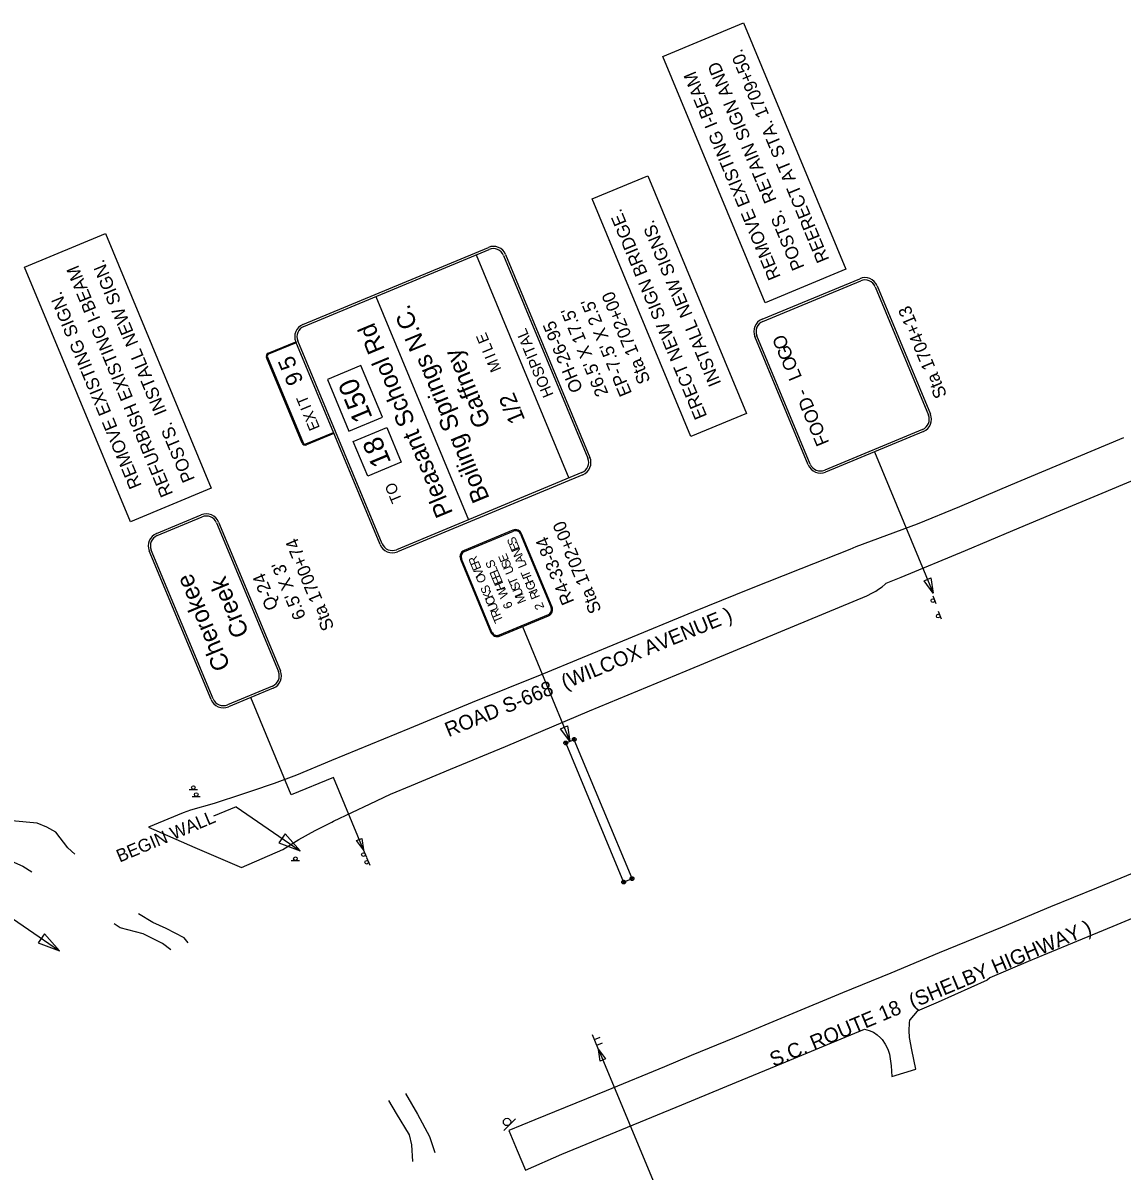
# Model space of a CAD drawing. Extents: x 1816080 to 1817753, y 1191002 to 1192408.
# Drawn here: x 1816561 to 1817158, y 1191507 to 1192132 of the extents above; entities that cross this region are included whole.
import ezdxf

# ---------------------------------------------------------------- set-up
doc = ezdxf.new("R2010")
doc.units = 0
for name, color, linetype in [('RD_EX_H2O', 7, 'Continuous'), ('RD_EX_Road', 7, 'Continuous'), ('RD_PD_Final_TX', 7, 'Continuous'), ('RD_TX_RoadID', 7, 'Continuous'), ('SN_P_Signs', 7, 'Continuous'), ('TERMINATOR', 7, 'Continuous')]:
    doc.layers.add(name, color=color, linetype=linetype)

msp = doc.modelspace()

# ---------------------------------------------------------------- linework, layer by layer
at = {"layer": 'RD_EX_H2O'}
for points in [[(1816589, 1191679.78), (1816585.25, 1191683.2), (1816578.74, 1191691.77), (1816573.75, 1191694.47), (1816568.64, 1191696.6), (1816554.75, 1191697.91), (1816541.33, 1191701.27), (1816538.68, 1191702.62), (1816532.83, 1191708.56), (1816530.28, 1191709.54), (1816524.78, 1191709.72), (1816522.41, 1191709.25)], [(1816520.29, 1191693.6), (1816530.82, 1191691.49), (1816535.64, 1191689.78), (1816539.88, 1191686.46), (1816543.67, 1191682.18), (1816552.98, 1191676.66), (1816560.73, 1191673.18), (1816565.63, 1191670.1)], [(1816650.69, 1191631.6), (1816648.48, 1191634.22), (1816638.79, 1191639.27), (1816631.49, 1191642.56), (1816623.69, 1191647.26)], [(1816641.27, 1191627.68), (1816636.63, 1191631.24), (1816626.22, 1191636.42), (1816613.77, 1191639.59), (1816610.48, 1191641.82)], [(1816772.91, 1191512.59), (1816772.31, 1191521.59), (1816770.96, 1191527.01), (1816763.86, 1191538.77), (1816759.76, 1191545.79)], [(1816768.75, 1191549.52), (1816775.4, 1191538.37), (1816781.92, 1191526.15), (1816784.51, 1191518.57), (1816784.74, 1191517.47)]]:
    msp.add_lwpolyline(points, dxfattribs=at)
at = {"layer": 'RD_EX_Road'}
for points in [[(1817159.28, 1191906.27), (1817133.62, 1191895.47), (1817097.75, 1191880.38), (1817070, 1191868.72), (1817046.98, 1191859.18), (1817013.79, 1191846.89), (1817010.39, 1191845.48), (1816983.85, 1191834.92), (1816955.91, 1191823.87), (1816925.5, 1191811.48), (1816886.89, 1191795.51), (1816842.95, 1191777.48), (1816805.13, 1191762.22), (1816770.95, 1191748.17), (1816728.58, 1191730.62), (1816709.5, 1191722.66), (1816697.39, 1191718.14), (1816685.15, 1191713.99), (1816680.25, 1191712.44), (1816664.73, 1191707.29), (1816651.93, 1191703.61), (1816648.02, 1191702.29), (1816629.17, 1191694.48), (1816654.27, 1191683.4), (1816679.72, 1191672.57), (1816702.06, 1191682.35), (1816710.8, 1191687.65), (1816719.74, 1191692.61), (1816728.86, 1191697.23), (1816729.67, 1191697.62), (1816749.54, 1191707.18), (1816760.69, 1191712.36), (1816772.09, 1191717.17), (1816793.24, 1191725.98), (1816823.15, 1191738.29), (1816868.84, 1191757.71), (1816921.52, 1191779.54), (1816972.94, 1191800.93), (1817019.73, 1191820.32), (1817022.74, 1191821.91), (1817024.61, 1191822.88), (1817026.09, 1191823.82), (1817027.98, 1191825.06), (1817029.63, 1191826.61), (1817030.13, 1191827.2), (1817038.28, 1191830.49), (1817073.38, 1191844.99), (1817099.07, 1191855.87), (1817122.78, 1191865.77), (1817147.59, 1191876.11), (1817172.24, 1191886.42)], [(1817167.93, 1191670.92), (1817144.65, 1191661.34), (1817119.54, 1191651.03), (1817093.24, 1191640.1), (1817059.06, 1191626), (1817032.77, 1191615.07), (1817006.46, 1191604.26), (1816977.23, 1191592.23), (1816947.67, 1191579.89), (1816924.09, 1191570.24), (1816909.61, 1191564.09), (1816877.97, 1191550.97), (1816839.15, 1191535.23), (1816824.95, 1191529.39), (1816829.5, 1191518.62), (1816834.02, 1191507.96), (1816853.9, 1191516.54), (1816919.09, 1191543.42), (1816934.01, 1191549.55), (1816948.82, 1191555.7), (1816973.39, 1191565.89), (1816998.28, 1191576.15), (1817018.5, 1191584.55)], [(1817174.36, 1191649.05), (1817153.46, 1191640.32), (1817128.43, 1191630.1), (1817107.43, 1191621.45), (1817086.59, 1191612.47), (1817085.14, 1191611.22), (1817058.42, 1191599.3), (1817047.13, 1191594.32), (1817043.08, 1191589.67)], [(1817018.5, 1191584.55), (1817020.94, 1191583.89), (1817023.23, 1191582.86), (1817025.34, 1191581.48), (1817027.21, 1191579.78), (1817027.96, 1191578.93), (1817029.71, 1191576.39), (1817031.11, 1191573.66), (1817032.09, 1191571.01), (1817032.92, 1191564.55), (1817033.32, 1191558.82), (1817046.4, 1191562.74), (1817044.12, 1191573.35), (1817042.9, 1191579.97), (1817042.68, 1191583.86), (1817042.85, 1191587.75), (1817043.08, 1191589.67)]]:
    msp.add_lwpolyline(points, dxfattribs=at)
at = {"layer": 'RD_PD_Final_TX'}
for p, q in [((1816676.7, 1191705.54), (1816664.44, 1191700.39)), ((1816676.7, 1191705.54), (1816711.62, 1191681.62)), ((1816545.83, 1191651.16), (1816580.76, 1191627.24))]:
    msp.add_line(p, q, dxfattribs=at)
at = {"layer": 'SN_P_Signs'}
for p, q in [((1816908.71, 1192113.57), (1816952.69, 1192131.84)), ((1816952.69, 1192131.84), (1817008.34, 1191997.93)), ((1816964.37, 1191979.65), (1816908.71, 1192113.57)), ((1816870.25, 1192036.15), (1816900.54, 1192048.74)), ((1816900.54, 1192048.74), (1816954.25, 1191919.5)), ((1816923.96, 1191906.91), (1816870.25, 1192036.15)), ((1816561.72, 1191998.99), (1816605.69, 1192017.26)), ((1816605.69, 1192017.26), (1816663.26, 1191878.73)), ((1816823.3, 1192005.87), (1816869.14, 1191895.56)), ((1816807.2, 1192005.67), (1816857.64, 1191884.28)), ((1816619.29, 1191860.46), (1816561.72, 1191998.99)), ((1817008.34, 1191997.93), (1816964.37, 1191979.65)), ((1816752.64, 1191983), (1816803.09, 1191861.61)), ((1816744.57, 1191945.55), (1816726.39, 1191937.99)), ((1816756.27, 1191917.4), (1816744.57, 1191945.55)), ((1816726.39, 1191937.99), (1816738.09, 1191909.85)), ((1816954.25, 1191919.5), (1816923.96, 1191906.91)), ((1816738.09, 1191909.85), (1816756.27, 1191917.4)), ((1816740.42, 1191904.24), (1816758.6, 1191911.8)), ((1816758.6, 1191911.8), (1816766.46, 1191892.89)), ((1816748.28, 1191885.33), (1816740.42, 1191904.24)), ((1817023.83, 1191898.6), (1817055.82, 1191821.64)), ((1816766.46, 1191892.89), (1816748.28, 1191885.33)), ((1816663.26, 1191878.73), (1816619.29, 1191860.46)), ((1816663.11, 1191763.81), (1816629.49, 1191844.7)), ((1817057.41, 1191815.95), (1817055.71, 1191820.11)), ((1817060.34, 1191807.55), (1817058.63, 1191811.71)), ((1816832.37, 1191803.54), (1816858.27, 1191741.21)), ((1816706.76, 1191712.02), (1816684.74, 1191765)), ((1816855.06, 1191740.64), (1816856.9, 1191739.88)), ((1816855.6, 1191739.34), (1816856.36, 1191741.18)), ((1816860.64, 1191741.97), (1816856.06, 1191740.07)), ((1816856.06, 1191740.07), (1816887.45, 1191664.54)), ((1816859.63, 1191742.55), (1816861.48, 1191741.78)), ((1816860.17, 1191741.24), (1816860.94, 1191743.08)), ((1816892.02, 1191666.44), (1816860.64, 1191741.97)), ((1816729.63, 1191721.53), (1816706.76, 1191712.02)), ((1816746.05, 1191682.02), (1816729.63, 1191721.53)), ((1816651.23, 1191714.98), (1816655.73, 1191714.98)), ((1816652.77, 1191711.12), (1816657.27, 1191711.12)), ((1816747.76, 1191677.86), (1816746.05, 1191682.02)), ((1816706.72, 1191676.27), (1816711.22, 1191676.27)), ((1816749.54, 1191673.64), (1816747.83, 1191677.81)), ((1816886.53, 1191664.92), (1816888.37, 1191664.16)), ((1816887.07, 1191663.62), (1816887.83, 1191665.46)), ((1816887.45, 1191664.54), (1816892.02, 1191666.44)), ((1816891.1, 1191666.82), (1816892.95, 1191666.06)), ((1816891.64, 1191665.52), (1816892.41, 1191667.36)), ((1816873.82, 1191573.49), (1816870.49, 1191581.52)), ((1816871.54, 1191578.99), (1816874.61, 1191580.27)), ((1816872.82, 1191575.9), (1816875.89, 1191577.18)), ((1816873.82, 1191573.49), (1816907.2, 1191493.18)), ((1816822.28, 1191529.46), (1816828.64, 1191535.83))]:
    msp.add_line(p, q, dxfattribs=at)
for points in [[(1816713.05, 1191967.85), (1816813.89, 1192009.76)], [(1816713.51, 1191966.74), (1816814.35, 1192008.65)], [(1816822.19, 1192005.41), (1816868.03, 1191895.1)], [(1816962.7, 1191970.66), (1817015.89, 1191992.76)], [(1816963.16, 1191969.55), (1817016.35, 1191991.65)], [(1817024.19, 1191988.41), (1817053.21, 1191918.6)], [(1817025.3, 1191988.87), (1817054.31, 1191919.06)], [(1816694.2, 1191952.22), (1816709.16, 1191958.44), (1816709.39, 1191957.88)], [(1816709.39, 1191957.88), (1816694.43, 1191951.67)], [(1816755.01, 1191848.13), (1816709.16, 1191958.44)], [(1816756.11, 1191848.59), (1816710.27, 1191958.9)], [(1816987.83, 1191891.43), (1816958.82, 1191961.24)], [(1816988.94, 1191891.89), (1816959.92, 1191961.7)], [(1816712.57, 1191903.33), (1816693.23, 1191949.87)], [(1816693.79, 1191950.1), (1816713.13, 1191903.56)], [(1816714.7, 1191902.91), (1816729.66, 1191909.13), (1816729.89, 1191908.57), (1816714.93, 1191902.35)], [(1817049.97, 1191910.76), (1816996.78, 1191888.65)], [(1817050.43, 1191909.65), (1816997.24, 1191887.55)], [(1816864.8, 1191887.25), (1816763.96, 1191845.35)], [(1816865.26, 1191886.15), (1816764.42, 1191844.24)], [(1816633.38, 1191854.12), (1816657.82, 1191864.27)], [(1816633.84, 1191853.01), (1816658.28, 1191863.17)], [(1816666.12, 1191859.93), (1816699.74, 1191779.04)], [(1816667.23, 1191860.39), (1816700.85, 1191779.5)], [(1816827.26, 1191855.99), (1816800.66, 1191844.94)], [(1816800.89, 1191844.39), (1816827.49, 1191855.44)], [(1816831.41, 1191853.82), (1816847.99, 1191813.93)], [(1816848.54, 1191814.16), (1816831.96, 1191854.05)], [(1816664.21, 1191764.27), (1816630.6, 1191845.16)], [(1816798.72, 1191840.23), (1816815.3, 1191800.34)], [(1816815.85, 1191800.57), (1816799.27, 1191840.46)], [(1816846.37, 1191810.01), (1816819.77, 1191798.95)], [(1816820, 1191798.4), (1816846.6, 1191809.45)], [(1816696.5, 1191771.19), (1816672.06, 1191761.03)], [(1816696.96, 1191770.08), (1816672.52, 1191759.93)], [(1816856.36, 1191739.34), (1816856.2, 1191739.29), (1816856.04, 1191739.26), (1816855.87, 1191739.27), (1816855.71, 1191739.3), (1816855.55, 1191739.36), (1816855.41, 1191739.44), (1816855.28, 1191739.55), (1816855.17, 1191739.67), (1816855.08, 1191739.82), (1816855.02, 1191739.97), (1816854.99, 1191740.14), (1816854.98, 1191740.3), (1816855, 1191740.47), (1816855.05, 1191740.63), (1816855.12, 1191740.78), (1816855.22, 1191740.91), (1816855.34, 1191741.03), (1816855.48, 1191741.13), (1816855.6, 1191741.19)], [(1816855.6, 1191741.19), (1816855.76, 1191741.24), (1816855.92, 1191741.26), (1816856.09, 1191741.26), (1816856.25, 1191741.22), (1816856.41, 1191741.17), (1816856.55, 1191741.08), (1816856.68, 1191740.98), (1816856.79, 1191740.85), (1816856.88, 1191740.71), (1816856.94, 1191740.55), (1816856.97, 1191740.39), (1816856.98, 1191740.22), (1816856.96, 1191740.05), (1816856.91, 1191739.9), (1816856.84, 1191739.75), (1816856.74, 1191739.61), (1816856.62, 1191739.49), (1816856.48, 1191739.4), (1816856.36, 1191739.34)], [(1816860.94, 1191741.24), (1816860.78, 1191741.19), (1816860.62, 1191741.16), (1816860.45, 1191741.17), (1816860.28, 1191741.2), (1816860.13, 1191741.26), (1816859.98, 1191741.34), (1816859.86, 1191741.45), (1816859.75, 1191741.58), (1816859.66, 1191741.72), (1816859.6, 1191741.87), (1816859.56, 1191742.04), (1816859.56, 1191742.2), (1816859.58, 1191742.37), (1816859.63, 1191742.53), (1816859.7, 1191742.68), (1816859.8, 1191742.81), (1816859.92, 1191742.93), (1816860.05, 1191743.03), (1816860.17, 1191743.09)], [(1816860.17, 1191743.09), (1816860.33, 1191743.14), (1816860.5, 1191743.16), (1816860.66, 1191743.16), (1816860.83, 1191743.13), (1816860.98, 1191743.07), (1816861.13, 1191742.98), (1816861.26, 1191742.88), (1816861.37, 1191742.75), (1816861.45, 1191742.61), (1816861.51, 1191742.45), (1816861.55, 1191742.29), (1816861.56, 1191742.12), (1816861.53, 1191741.96), (1816861.49, 1191741.8), (1816861.41, 1191741.65), (1816861.31, 1191741.51), (1816861.2, 1191741.4), (1816861.06, 1191741.3), (1816860.94, 1191741.24)], [(1816887.83, 1191663.62), (1816887.67, 1191663.57), (1816887.51, 1191663.54), (1816887.34, 1191663.55), (1816887.18, 1191663.58), (1816887.02, 1191663.64), (1816886.88, 1191663.72), (1816886.75, 1191663.83), (1816886.64, 1191663.95), (1816886.55, 1191664.1), (1816886.49, 1191664.25), (1816886.46, 1191664.41), (1816886.45, 1191664.58), (1816886.47, 1191664.75), (1816886.52, 1191664.91), (1816886.59, 1191665.06), (1816886.69, 1191665.19), (1816886.81, 1191665.31), (1816886.94, 1191665.4), (1816887.06, 1191665.46)], [(1816887.06, 1191665.46), (1816887.22, 1191665.51), (1816887.39, 1191665.54), (1816887.56, 1191665.53), (1816887.72, 1191665.5), (1816887.88, 1191665.44), (1816888.02, 1191665.36), (1816888.15, 1191665.25), (1816888.26, 1191665.13), (1816888.34, 1191664.98), (1816888.41, 1191664.83), (1816888.44, 1191664.67), (1816888.45, 1191664.5), (1816888.43, 1191664.33), (1816888.38, 1191664.17), (1816888.3, 1191664.02), (1816888.21, 1191663.89), (1816888.09, 1191663.77), (1816887.95, 1191663.68), (1816887.83, 1191663.62)], [(1816892.41, 1191665.52), (1816892.25, 1191665.47), (1816892.08, 1191665.44), (1816891.92, 1191665.45), (1816891.75, 1191665.48), (1816891.6, 1191665.54), (1816891.45, 1191665.62), (1816891.32, 1191665.73), (1816891.21, 1191665.85), (1816891.13, 1191666), (1816891.07, 1191666.15), (1816891.03, 1191666.32), (1816891.03, 1191666.48), (1816891.05, 1191666.65), (1816891.09, 1191666.81), (1816891.17, 1191666.96), (1816891.27, 1191667.09), (1816891.38, 1191667.21), (1816891.52, 1191667.31), (1816891.64, 1191667.37)], [(1816891.64, 1191667.37), (1816891.8, 1191667.42), (1816891.97, 1191667.44), (1816892.13, 1191667.44), (1816892.3, 1191667.4), (1816892.45, 1191667.35), (1816892.6, 1191667.26), (1816892.73, 1191667.16), (1816892.83, 1191667.03), (1816892.92, 1191666.89), (1816892.98, 1191666.73), (1816893.02, 1191666.57), (1816893.02, 1191666.4), (1816893, 1191666.24), (1816892.95, 1191666.08), (1816892.88, 1191665.93), (1816892.78, 1191665.79), (1816892.66, 1191665.67), (1816892.53, 1191665.58), (1816892.41, 1191665.52)]]:
    msp.add_lwpolyline(points, dxfattribs=at)
for points in [[(1817054.56, 1191830), (1817055.82, 1191821.64), (1817050.78, 1191828.42)], [(1816856.92, 1191749.56), (1816858.27, 1191741.21), (1816853.15, 1191747.94)], [(1816745.11, 1191688.29), (1816746.05, 1191682.02), (1816742.27, 1191687.11)], [(1816874.76, 1191567.22), (1816873.82, 1191573.49), (1816877.6, 1191568.4)]]:
    msp.add_lwpolyline(points, close=True, dxfattribs=at)
for centre, radius in [((1817055.62, 1191817.66), 1), ((1817058.54, 1191809.26), 1), ((1816653.49, 1191715.99), 1), ((1816655.03, 1191712.13), 1), ((1816708.98, 1191677.28), 1), ((1816745.96, 1191679.56), 1), ((1816747.74, 1191675.35), 1), ((1816824.04, 1191534.09), 2)]:
    msp.add_circle(centre, radius, dxfattribs=at)
for centre, radius, start, end in [((1816816.65, 1192003.11), 7.2, 22.56659, 112.56659), ((1816816.65, 1192003.11), 6, 22.56659, 112.56659), ((1817018.65, 1191986.11), 7.2, 22.56659, 112.56659), ((1817018.65, 1191986.11), 6, 22.56659, 112.56659), ((1816965.46, 1191964.01), 7.2, 112.56659, 202.56659), ((1816965.46, 1191964.01), 6, 112.56659, 202.56659), ((1816715.81, 1191961.2), 7.2, 112.56659, 202.56659), ((1816715.81, 1191961.2), 6, 112.56659, 202.56659), ((1816694.89, 1191950.56), 1.8, 112.56659, 202.56659), ((1816694.89, 1191950.56), 1.2, 112.56659, 202.56659), ((1817047.67, 1191916.3), 6, 292.56659, 22.56659), ((1817047.67, 1191916.3), 7.2, 292.56659, 22.56659), ((1816714.24, 1191904.02), 1.8, 202.56659, 292.56659), ((1816714.24, 1191904.02), 1.2, 202.56659, 292.56659), ((1816862.49, 1191892.8), 6, 292.56659, 22.56659), ((1816862.49, 1191892.8), 7.2, 292.56659, 22.56659), ((1816994.48, 1191894.19), 7.2, 202.56659, 292.56659), ((1816994.48, 1191894.19), 6, 202.56659, 292.56659), ((1816660.58, 1191857.63), 7.2, 22.56659, 112.56659), ((1816660.58, 1191857.63), 6, 22.56659, 112.56659), ((1816828.64, 1191852.67), 3.6, 22.56659, 112.56659), ((1816636.14, 1191847.47), 7.2, 112.56659, 202.56659), ((1816636.14, 1191847.47), 6, 112.56659, 202.56659), ((1816828.64, 1191852.67), 3, 22.56659, 112.56659), ((1816761.65, 1191850.89), 7.2, 202.56659, 292.56659), ((1816761.65, 1191850.89), 6, 202.56659, 292.56659), ((1816802.04, 1191841.62), 3.6, 112.56659, 202.56659), ((1816802.04, 1191841.62), 3, 112.56659, 202.56659), ((1816845.22, 1191812.78), 3, 292.56659, 22.56659), ((1816845.22, 1191812.78), 3.6, 292.56659, 22.56659), ((1816818.62, 1191801.72), 3.6, 202.56659, 292.56659), ((1816818.62, 1191801.72), 3, 202.56659, 292.56659), ((1816694.2, 1191776.73), 6, 292.56659, 22.56659), ((1816694.2, 1191776.73), 7.2, 292.56659, 22.56659), ((1816669.76, 1191766.57), 7.2, 202.56659, 292.56659), ((1816669.76, 1191766.57), 6, 202.56659, 292.56659)]:
    msp.add_arc(centre, radius, start, end, dxfattribs=at)
at = {"layer": 'TERMINATOR'}
for points in [[(1816700.03, 1191685.93), (1816711.62, 1191681.62), (1816703.42, 1191690.88)], [(1816569.16, 1191631.55), (1816580.76, 1191627.24), (1816572.55, 1191636.5)]]:
    msp.add_lwpolyline(points, close=True, dxfattribs=at)

# ---------------------------------------------------------------- texts
at = {"layer": 'RD_PD_Final_TX'}
msp.add_text('BEGIN WALL', height=7, rotation=22.81659, dxfattribs=at).set_placement((1816613.43, 1191675.12))
at = {"layer": 'RD_TX_RoadID'}
for s, rotation, p in [('ROAD S-668  (WILCOX AVENUE )', 22.3035, (1816792.26, 1191743.32)), ('S.C. ROUTE 18  (SHELBY HIGHWAY )', 22.77314, (1816968.98, 1191563.9))]:
    msp.add_text(s, height=8, rotation=rotation, dxfattribs=at).set_placement(p)
at = {"layer": 'SN_P_Signs'}
for s, height, rotation, p in [('REERECT AT STA. 1709+50.', 6.9998, 112.56667, (1816999.38, 1192003.19)), ('POSTS.  RETAIN SIGN AND', 6.9998, 112.56667, (1816985.94, 1191999.05)), ('REMOVE EXISTING I-BEAM', 6.9998, 112.56667, (1816972.97, 1191993.78)), ('ERECT NEW SIGN BRIDGE.', 6.9998, 112.56667, (1816932.94, 1191917.99)), ('INSTALL NEW SIGNS.', 6.9998, 112.56667, (1816940.66, 1191935.9)), ('REFURBISH EXISTING I-BEAM', 6.9998, 112.56667, (1816642.57, 1191875.74)), ('POSTS.  INSTALL NEW SIGN.', 6.9998, 112.56667, (1816654.43, 1191883.68)), ('REMOVE EXISTING SIGN.', 6.9998, 112.56667, (1816625.55, 1191880.21)), ('Sta 1702+00', 7, 112.56667, (1816902.17, 1191937.22)), ('Boiling Springs N.C.', 9.6, 112.56659, (1816814.68, 1191873.33)), ("26.5' X 17.5'", 7, 112.56667, (1816879.24, 1191930.38)), ("EP-7.5' X 2.5'", 7, 112.56667, (1816892.09, 1191930.47)), ('Sta 1704+13', 7, 112.56667, (1817063.42, 1191929.39)), ('Pleasant School Rd', 9.6, 112.56659, (1816794.8, 1191865.28)), ('OH-26-95', 7, 112.56667, (1816865.46, 1191932.53)), ('E', 6, 112.56659, (1816814.56, 1191959.04)), ('HOSPITAL', 6, 112.56659, (1816849.48, 1191929.64)), ('L', 6, 112.56659, (1816816.64, 1191954.03)), ('O', 7.2, 112.56659, (1816977.51, 1191956.13)), ('O', 7.2, 112.56659, (1816977.51, 1191956.13)), ('G', 7.2, 112.56659, (1816979.88, 1191950.42)), ('G', 7.2, 112.56659, (1816979.88, 1191950.42)), ('5', 9, 112.56659, (1816710.02, 1191945.43)), ('Gaffney', 9.6, 112.56659, (1816815.42, 1191914.07)), ('I', 6, 112.56659, (1816818.02, 1191950.71)), ('O', 7.2, 112.56659, (1816982.34, 1191944.5)), ('O', 7.2, 112.56659, (1816982.34, 1191944.5)), ('M', 6, 112.56659, (1816821.04, 1191943.45)), ('L', 7.2, 112.56659, (1816984.54, 1191939.2)), ('L', 7.2, 112.56659, (1816984.54, 1191939.2)), ('9', 9, 112.56659, (1816713.51, 1191937.02)), ('150', 10.8, 112.56659, (1816751.08, 1191917.3)), ('1/2', 9, 112.56659, (1816834.04, 1191916.06)), ('-', 7.2, 112.56659, (1816988.14, 1191930.55)), ('-', 7.2, 112.56659, (1816988.14, 1191930.55)), ('T', 6, 112.56659, (1816716.68, 1191925.48)), ('FOOD', 7.2, 112.56659, (1816999.35, 1191903.57)), ('I', 6, 112.56659, (1816717.83, 1191922.73)), ('X', 6, 112.56659, (1816720.44, 1191916.44)), ('E', 6, 112.56659, (1816722.42, 1191911.68)), ('18', 10.8, 112.56659, (1816761.21, 1191892.92)), ('TO', 6, 112.56659, (1816767.19, 1191872.24)), ('Sta 1702+00', 7, 112.56667, (1816875.57, 1191812.37)), ('Sta 1700+74', 7, 112.56667, (1816730.24, 1191803.03)), ('S', 4.8, 112.56659, (1816829.87, 1191848.92)), ('R4-33-84', 7, 112.56667, (1816860.73, 1191817.07)), ('E', 4.8, 112.56659, (1816825.21, 1191839.8)), ('E', 4.8, 112.56659, (1816831.1, 1191845.95)), ('N', 4.8, 112.56659, (1816832.5, 1191842.59)), ("6.5' X 3'", 7, 112.56667, (1816714.89, 1191808.95)), ('R', 4.8, 112.56659, (1816809, 1191838.16)), ('E', 4.8, 112.56659, (1816810.23, 1191835.2)), ('S', 4.8, 112.56659, (1816818.16, 1191836.44)), ('S', 4.8, 112.56659, (1816826.61, 1191836.44)), ('A', 4.8, 112.56659, (1816833.96, 1191839.07)), ('L', 4.8, 112.56659, (1816834.99, 1191836.61)), ('Cherokee', 9.6, 112.56659, (1816673.78, 1191781.77)), ('Creek', 9.6, 112.56659, (1816683.94, 1191799.85)), ('Q-24', 7, 112.56667, (1816699.86, 1191814.1)), ('V', 4.8, 112.56659, (1816811.67, 1191831.75)), ('O', 4.8, 112.56659, (1816813.04, 1191828.44)), ('L', 4.8, 112.56659, (1816819.39, 1191833.48)), ('E', 4.8, 112.56659, (1816820.63, 1191830.52)), ('E', 4.8, 112.56659, (1816821.86, 1191827.55)), ('U', 4.8, 112.56659, (1816828, 1191833.09)), ('T', 4.8, 112.56659, (1816837.29, 1191831.07)), ('H', 4.8, 112.56659, (1816838.61, 1191827.89)), ('S', 4.8, 112.56659, (1816815.43, 1191822.69)), ('H', 4.8, 112.56659, (1816823.25, 1191824.19)), ('T', 4.8, 112.56659, (1816830.31, 1191827.55)), ('S', 4.8, 112.56659, (1816831.62, 1191824.37)), ('G', 4.8, 112.56659, (1816840, 1191824.54)), ('K', 4.8, 112.56659, (1816816.75, 1191819.52)), ('C', 4.8, 112.56659, (1816818.07, 1191816.35)), ('W', 4.8, 112.56659, (1816824.95, 1191820.12)), ('U', 4.8, 112.56659, (1816833.02, 1191821.02)), ('M', 4.8, 112.56659, (1816834.6, 1191817.21)), ('I', 4.8, 112.56659, (1816840.65, 1191822.98)), ('R', 4.8, 112.56659, (1816842.05, 1191819.62)), ('U', 4.8, 112.56659, (1816819.46, 1191812.99)), ('R', 4.8, 112.56659, (1816820.86, 1191809.63)), ('6', 4.8, 112.56659, (1816827.33, 1191814.37)), ('2', 4.8, 112.56659, (1816844.43, 1191813.87)), ('T', 4.8, 112.56659, (1816822.09, 1191806.67))]:
    msp.add_text(s, height=height, rotation=rotation, dxfattribs=at).set_placement(p)

doc.saveas('drawing.dxf')
